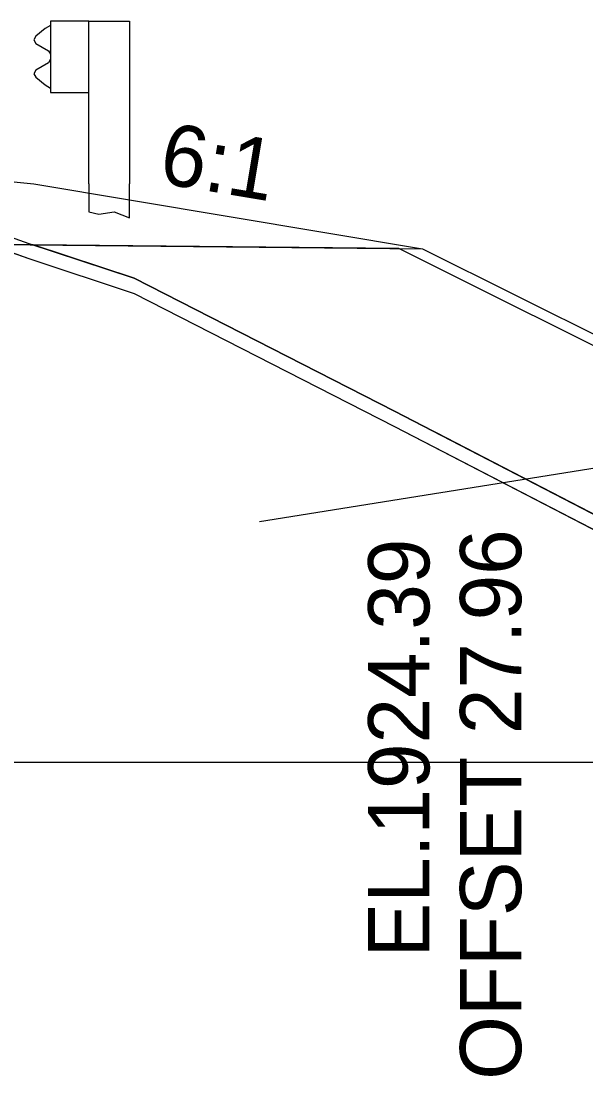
# Model space of a CAD drawing. Extents: x 1574 to 14903, y 7971 to 16537.
# Drawn here: x 14621.79 to 14631.02, y 8494.87 to 8512.11 of the extents above; entities that cross this region are included whole.
import ezdxf

# ---------------------------------------------------------------- set-up
doc = ezdxf.new("R2010")
doc.units = 0
for name, color, linetype in [('DESIGN - EARTHWORK - Shapes', 7, 'Continuous'), ('DESIGN - SCRATCH - User 1', 7, 'Continuous'), ('DESIGN - SHEET - Light Grid', 7, 'Continuous'), ('DESIGN - TYPICAL - Finished Grade and Subgrade', 7, 'Continuous'), ('DESIGN - TYPICAL - Finished Grade Slopes Text', 7, 'Continuous'), ('DESIGN - TYPICAL - Guardrail', 7, 'Continuous'), ('DESIGN - TYPICAL - Slope Tie Text', 7, 'Continuous'), ('DESIGN - TYPICAL - Subgrade Tie Text', 7, 'Continuous'), ('SURVEY - GROUND - Bottom of Topsoil Layer', 7, 'Continuous'), ('SURVEY - GROUND - Top of Ground', 7, 'Continuous')]:
    doc.layers.add(name, color=color, linetype=linetype)

msp = doc.modelspace()

# ---------------------------------------------------------------- linework, layer by layer
at = {"layer": 'DESIGN - EARTHWORK - Shapes'}
for points in [[(14617.856, 8509.669), (14618.648, 8509.638), (14621.92, 8508.475), (14621.989, 8508.452), (14621.26, 8508.46)], [(14642.161, 8500.61), (14643.012, 8500.617), (14643.012, 8500.867), (14642.161, 8500.86), (14639.329, 8501.174), (14635.553, 8501.765), (14631.238, 8504), (14627.888, 8505.735), (14623.638, 8507.904), (14621.989, 8508.452), (14621.26, 8508.46), (14621.92, 8508.225), (14623.638, 8507.654), (14627.888, 8505.485), (14635.553, 8501.515), (14639.329, 8500.924)], [(14631.238, 8504), (14636.745, 8504), (14627.96, 8508.393), (14621.989, 8508.452), (14623.638, 8507.904), (14627.888, 8505.735)]]:
    msp.add_lwpolyline(points, close=True, dxfattribs=at)
at = {"layer": 'DESIGN - SCRATCH - User 1'}
msp.add_lwpolyline([(14636.745, 8504), (14631.238, 8504), (14628.574, 8505.38)], dxfattribs=at)
at = {"layer": 'DESIGN - SHEET - Light Grid'}
msp.add_line((14600, 8500), (14900, 8500), dxfattribs=at)
at = {"layer": 'DESIGN - TYPICAL - Finished Grade and Subgrade'}
for p, q in [((14621.072, 8509.539), (14622, 8509.446)), ((14622, 8509.446), (14628.347, 8508.388)), ((14611.863, 8508.553), (14628.347, 8508.388)), ((14628.347, 8508.388), (14637.124, 8504))]:
    msp.add_line(p, q, dxfattribs=at)
at = {"layer": 'DESIGN - TYPICAL - Guardrail'}
for p, q in [((14622.896, 8512.106), (14622.271, 8512.106)), ((14622.271, 8512.106), (14622.271, 8510.939)), ((14622.896, 8509.449), (14622.896, 8512.106)), ((14622.896, 8512.106), (14623.562, 8512.106)), ((14623.562, 8512.106), (14623.562, 8509.449)), ((14622.187, 8511.983), (14622.033, 8511.857)), ((14622.271, 8512.033), (14622.187, 8511.983)), ((14622.033, 8511.857), (14622, 8511.798)), ((14622, 8511.798), (14622.033, 8511.74)), ((14622.033, 8511.74), (14622.237, 8511.622)), ((14622.237, 8511.622), (14622.271, 8511.564)), ((14622.237, 8511.422), (14622.033, 8511.305)), ((14622.271, 8511.481), (14622.237, 8511.422)), ((14622.271, 8511.564), (14622.271, 8511.522)), ((14622.271, 8511.522), (14622.271, 8511.481)), ((14622.033, 8511.305), (14622, 8511.246)), ((14622, 8511.246), (14622.033, 8511.188)), ((14622.033, 8511.188), (14622.187, 8511.062)), ((14622.187, 8511.062), (14622.271, 8511.012)), ((14622.271, 8510.939), (14622.896, 8510.939)), ((14622.896, 8509.449), (14622.896, 8508.989)), ((14623.562, 8508.889), (14623.562, 8509.449)), ((14622.896, 8508.989), (14623.062, 8508.949)), ((14623.062, 8508.949), (14623.312, 8508.989)), ((14623.312, 8508.989), (14623.562, 8508.889))]:
    msp.add_line(p, q, dxfattribs=at)
at = {"layer": 'DESIGN - TYPICAL - Slope Tie Text'}
msp.add_lwpolyline([(14625.684, 8503.931), (14631.608, 8504.878), (14632.843, 8504)], dxfattribs=at)
at = {"layer": 'SURVEY - GROUND - Bottom of Topsoil Layer'}
for p, q in [((14616.951, 8509.991), (14621.92, 8508.225)), ((14621.92, 8508.225), (14623.638, 8507.654)), ((14623.638, 8507.654), (14627.888, 8505.485)), ((14627.888, 8505.485), (14635.553, 8501.515))]:
    msp.add_line(p, q, dxfattribs=at)
at = {"layer": 'SURVEY - GROUND - Top of Ground'}
msp.add_lwpolyline([(14616.951, 8510.241), (14621.92, 8508.475), (14623.638, 8507.904), (14627.888, 8505.735), (14635.553, 8501.765), (14639.329, 8501.174), (14642.161, 8500.86), (14651.084, 8500.933), (14652.282, 8500.879), (14653.214, 8500.973), (14654.895, 8501.691), (14662.41, 8505.243)], dxfattribs=at)

# ---------------------------------------------------------------- texts
at = {"layer": 'DESIGN - TYPICAL - Finished Grade Slopes Text'}
msp.add_text('6:1', height=1, rotation=350.5377, dxfattribs=at).set_placement((14624.016, 8509.467))
at = {"layer": 'DESIGN - TYPICAL - Subgrade Tie Text'}
for s, p in [('OFFSET 27.96', (14629.96, 8494.811)), ('EL.1924.39', (14628.46, 8496.81))]:
    msp.add_text(s, height=1, rotation=90, dxfattribs=at).set_placement(p)

doc.saveas('drawing.dxf')
